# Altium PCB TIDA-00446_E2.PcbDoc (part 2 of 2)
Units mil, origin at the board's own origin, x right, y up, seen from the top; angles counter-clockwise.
Board outline 1780.03 x 5400.03 mil, 4 copper layers (Top Layer, GND, PWR, Bottom Layer), stack 79.834 mil thick; 192 components, 100 nets, 515 pads, 129 vias.
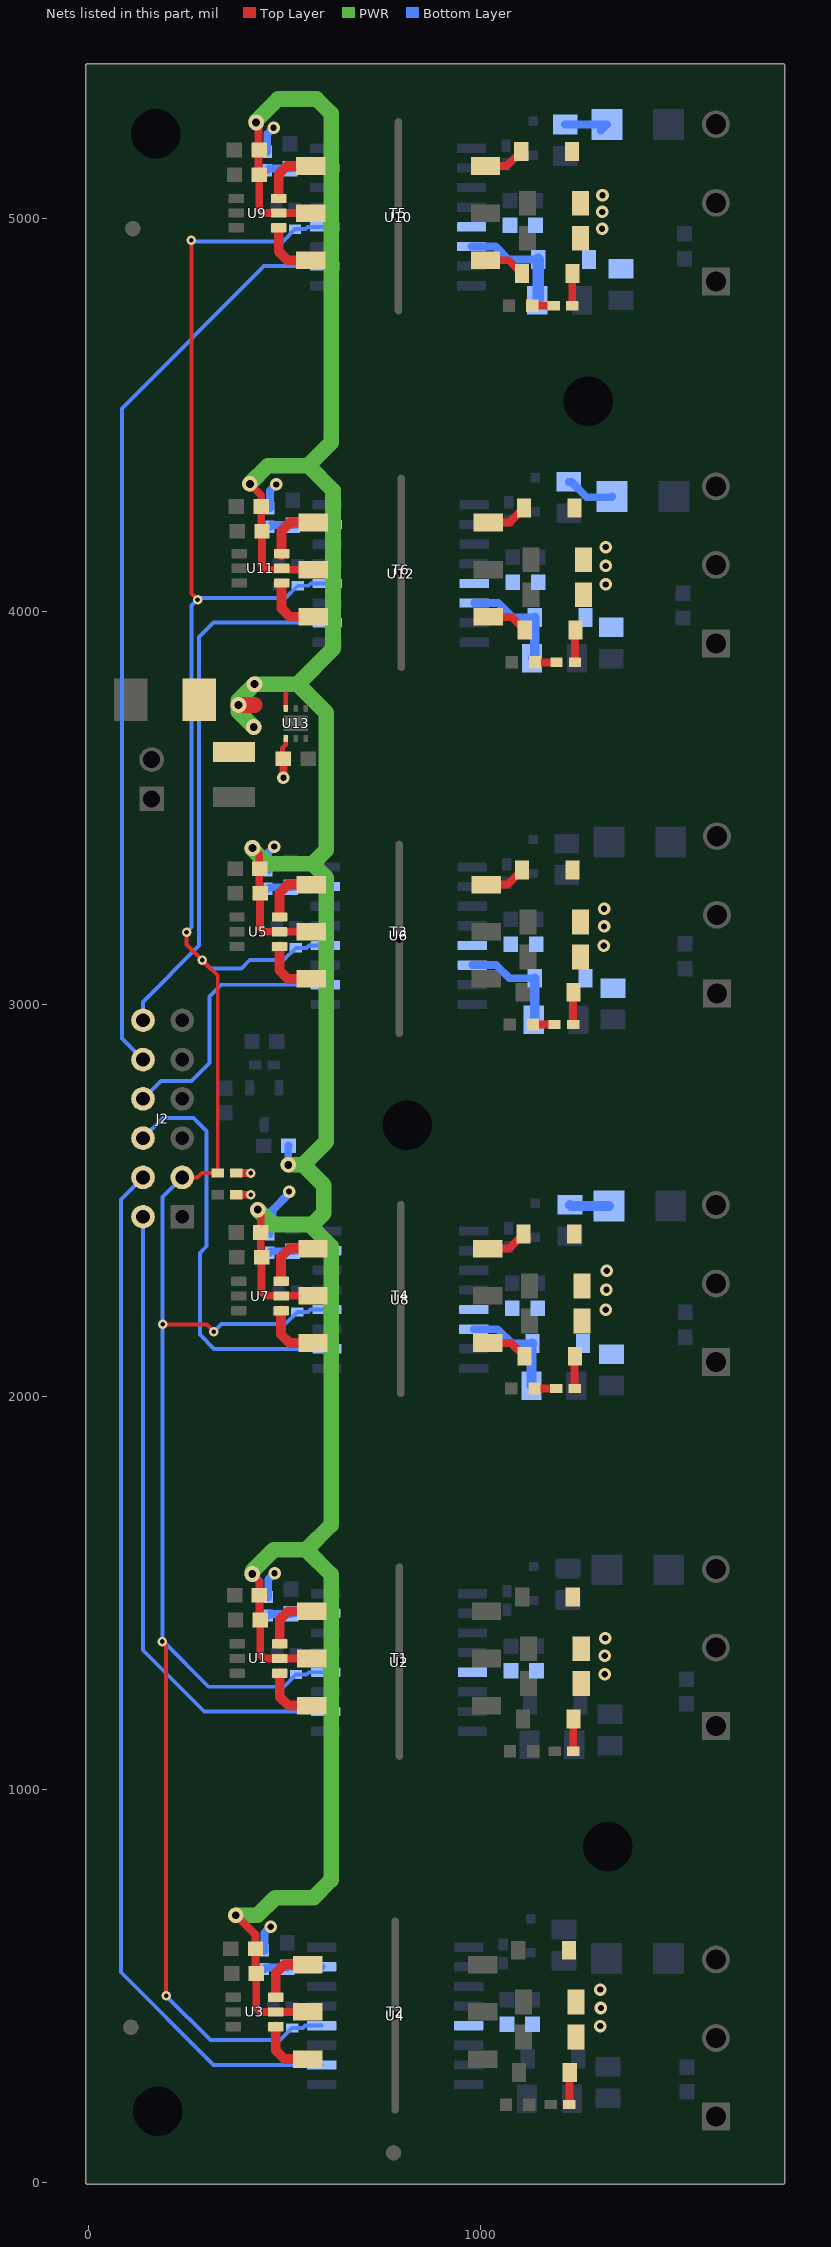
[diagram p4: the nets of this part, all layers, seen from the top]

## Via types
v1: diameter 32, hole 16, Top Layer to Bottom Layer, 85 vias
v2: diameter 24, hole 12, Top Layer to Bottom Layer, 30 vias
v3: diameter 40, hole 20, Top Layer to Bottom Layer, 12 vias
v4: diameter 19.68, hole 7.87, Top Layer to Bottom Layer, 2 vias

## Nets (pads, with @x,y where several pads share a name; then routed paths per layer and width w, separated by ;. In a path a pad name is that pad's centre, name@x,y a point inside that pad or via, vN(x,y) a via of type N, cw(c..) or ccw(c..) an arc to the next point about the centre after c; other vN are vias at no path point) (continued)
NetD17_2: D17.2 T3.6 | length 106.2
  Top Layer w20: T3.6@1014.13,3304.59 1068.1,3304.59 D17.2@1105.02,3341.51
NetD18_1: D18.1 R19.1 U6.6 | length 320.6
  Bottom Layer w20: 1019.06,3099.51 U6.6@978.5,3099.51 1039.49,3099.51 1073,3066 D18.1@1137.53,3066
  Bottom Layer w25: R19.1@1134.91,2960 1137.53,2962.62 D18.1@1137.53,3066
NetD18_2: D18.2 R20.1
NetD19_1: D19.1 R18.1 | length 54.9
  Top Layer w20: D19.1@1133.02,2948.51 R18.1@1187.87,2948.51
NetD21_2: D21.2 T4.4 | length 114.1
  Top Layer w20: T4.4@1018.13,2137.43 1077.1,2137.43 D21.2@1111.02,2103.51 ; D21.2@1108.52,2101.01 1110.02,2099.51 D21.2@1110.02,2094.51
NetD22_2: D22.2 R22.2 | length 100.5
  Bottom Layer w25: R22.2@1227,2489 1230,2486 D22.2@1326.26,2486
NetD23_2: D23.2 T4.6 | length 106.2
  Top Layer w20: T4.6@1018.13,2377.59 1072.1,2377.59 D23.2@1109.02,2414.51
NetD24_1: D24.1 R24.1 U8.6 | length 313.8
  Bottom Layer w20: 1023.06,2172.51 U8.6@982.5,2172.51 1043.49,2172.51 1080,2136 D24.1@1131.53,2136
  Bottom Layer w25: R24.1@1128.91,2028 1128.91,2133.38 D24.1@1131.53,2136
NetD24_2: D24.2 R25.1
NetD25_1: D25.1 R23.1 | length 54.9
  Top Layer w20: D25.1@1137.02,2021.51 R23.1@1191.87,2021.51
NetD27_2: D27.2 T5.4 | length 114.1
  Top Layer w20: T5.4@1012.13,4894.43 1071.1,4894.43 D27.2@1105.02,4860.51 ; D27.2@1102.52,4858.01 1104.02,4856.51 D27.2@1104.02,4851.51
NetD28_2: D28.2 R27.2 | length 128
  Bottom Layer w20: R27.2@1215,5240 D28.2@1321.13,5240 D28.2@1305.64,5224.51
NetD29_2: D29.2 T5.6 | length 106.2
  Top Layer w20: T5.6@1012.13,5134.59 1066.1,5134.59 D29.2@1103.02,5171.51
NetD30_1: D30.1 R29.1 U10.6 | length 288
  Bottom Layer w20: U10.6@976.5,4929.51 1037.49,4929.51 1071,4896 D30.1@1146.53,4896 ; R29.1@1143.91,4793 R29.1@1146.53,4795.62
  Bottom Layer w30: R29.1@1146.53,4795.62 D30.1@1146.53,4896
NetD30_2: D30.2 R30.1
NetD31_1: D31.1 R28.1 | length 54.9
  Top Layer w20: D31.1@1131.02,4778.51 R28.1@1185.87,4778.51
NetD33_2: D33.2 T6.4 | length 114.1
  Top Layer w20: T6.4@1019.13,3986.43 1078.1,3986.43 D33.2@1112.02,3952.51 ; D33.2@1109.52,3950.01 1111.02,3948.51 D33.2@1111.02,3943.51
NetD34_2: D34.2 R32.2 | length 127.5
  Bottom Layer w20: R32.2@1224,4330 1231,4330 1270,4291 1333.24,4291 D34.2@1334.75,4292.51
NetD35_2: D35.2 T6.6 | length 106.2
  Top Layer w20: T6.6@1019.13,4226.59 1073.1,4226.59 D35.2@1110.02,4263.51
NetD36_1: D36.1 R34.1 U12.6 | length 316.5
  Bottom Layer w20: 1024.06,4021.51 U12.6@983.5,4021.51 1044.49,4021.51 1081,3985 D36.1@1137.53,3985 ; R34.1@1130.91,3881 R34.1@1137.53,3887.62
  Bottom Layer w25: R34.1@1137.53,3887.62 D36.1@1137.53,3985
NetD36_2: D36.2 R35.1
NetD37_1: D37.1 R33.1 | length 54.9
  Top Layer w20: D37.1@1138.02,3870.51 R33.1@1192.87,3870.51
NetT1_1: T1.1 U1.3 | length 151.6
  Top Layer w25: U1.3@488.13,1371.4 488.13,1433.13 509.08,1454.08 T1.1@569.36,1454.08
NetT1_3: T1.3 U1.1 | length 151.1
  Top Layer w25: U1.1@488.13,1296.6 488.13,1235.87 510.08,1213.92 T1.3@569.36,1213.92
NetT2_1: T2.1 U3.3 | length 151.6
  Top Layer w25: U3.3@478.13,471.4 478.13,533.13 499.08,554.08 T2.1@559.36,554.08
NetT2_3: T2.3 U3.1 | length 151.1
  Top Layer w25: U3.1@478.13,396.6 478.13,335.87 500.08,313.92 T2.3@559.36,313.92
NetT3_1: T3.1 U5.3 | length 151.6
  Top Layer w25: U5.3@487.62,3221.91 487.62,3283.64 508.57,3304.59 T3.1@568.85,3304.59
NetT3_3: T3.3 U5.1 | length 151.1
  Top Layer w25: U5.1@487.62,3147.11 487.62,3086.38 509.57,3064.43 T3.3@568.85,3064.43
NetT4_1: T4.1 U7.3 | length 151.6
  Top Layer w25: U7.3@491.62,2294.91 491.62,2356.64 512.57,2377.59 T4.1@572.85,2377.59
NetT4_3: T4.3 U7.1 | length 151.1
  Top Layer w25: U7.1@491.62,2220.11 491.62,2159.38 513.57,2137.43 T4.3@572.85,2137.43
NetT5_1: T5.1 U9.3 | length 151.6
  Top Layer w25: U9.3@485.62,5051.91 485.62,5113.64 506.57,5134.59 T5.1@566.85,5134.59
NetT5_3: T5.3 U9.1 | length 151.1
  Top Layer w25: U9.1@485.62,4977.11 485.62,4916.38 507.57,4894.43 T5.3@566.85,4894.43
NetT6_1: T6.1 U11.3 | length 151.6
  Top Layer w25: U11.3@492.62,4143.91 492.62,4205.64 513.57,4226.59 T6.1@573.85,4226.59
NetT6_3: T6.3 U11.1 | length 151.1
  Top Layer w25: U11.1@492.62,4069.11 492.62,4008.38 514.57,3986.43 T6.3@573.85,3986.43
P3P3V: C20.1 R1.1 R6.1 R8.1 R16.2 R17.2 R21.1 R26.1 R31.1 U13.1 | length 643.9
  Top Layer w12: C20.1@497.5,3625 495,3627.5 495,3652.27 503.41,3660.68 U13.1@503.41,3676.61
  Top Layer w20: R17.2@377.62,2515 v2(414,2515) ; R16.2@377.62,2570 v2(414,2570) ; C20.1@497.5,3625 v1(497.5,3576.5) v1@499,3575
  Bottom Layer w20: R8.1@449,590.62 449,635 v1(465,651) ; R26.1@456.49,5171.13 456.49,5215.51 v1(472.49,5231.51) ; R6.1@458.49,3341.13 458.49,3385.51 v1(474.49,3401.51) ; R1.1@459,1490.62 459,1535 v1(475,1551) ; R21.1@462.49,2414.13 462.49,2453.75 470,2461.26 470,2476 512,2518 v1(512,2523) ; R31.1@463.49,4263.13 463.49,4307.51 v1(479.49,4323.51)
P3P3V_FLT_B_U: C11.1 R8.2 U4.15 | length 148.3
  Bottom Layer w20: R8.2@449,543.38 453.13,547.5 C11.1@507,547.5 508.5,549 U4.15@594.99,549
P3P3V_FLT_B_V: C34.1 R21.2 U8.15 | length 148.3
  Bottom Layer w20: R21.2@462.49,2366.89 466.62,2371.01 C34.1@520.49,2371.01 521.99,2372.51 U8.15@608.48,2372.51
P3P3V_FLT_B_W: C54.1 R31.2 U12.15 | length 148.3
  Bottom Layer w20: R31.2@463.49,4215.89 467.62,4220.01 C54.1@521.49,4220.01 522.99,4221.51 U12.15@609.48,4221.51
P3P3V_FLT_T_U: C2.1 R1.2 U2.15 | length 148.3
  Bottom Layer w20: R1.2@459,1443.38 463.13,1447.5 C2.1@517,1447.5 518.5,1449 U2.15@604.99,1449
P3P3V_FLT_T_V: C26.1 R6.2 U6.15 | length 148.3
  Bottom Layer w20: R6.2@458.49,3293.89 462.62,3298.01 C26.1@516.49,3298.01 517.99,3299.51 U6.15@604.48,3299.51
P3P3V_FLT_T_W: C46.1 R26.2 U10.15 | length 148.3
  Bottom Layer w20: R26.2@456.49,5123.89 460.62,5128.01 C46.1@514.49,5128.01 515.99,5129.51 U10.15@602.48,5129.51
P5V: C1.2 C5.2 C6.1 C10.2 C15.1 C19.1 C27.1 C33.2 C37.1 C43.2 C47.1 C53.2 C57.1 D13.1 R9.2 T1.2 T2.2 T3.2 T4.2 T5.2 T6.2 U1.2 U3.2 U5.2 U7.2 U9.2 U11.2 U13.6 | length 8504.4
  Top Layer w12: U13.6@503.41,3753.39 503.41,3789.41 504,3790
  Top Layer w20: v3(376,680) 377,680 426.5,630.5 C10.2@426.5,595 426.5,534 C15.1@428.5,532 428.5,444.5 439,434 U3.2@478.13,434 T2.2@559.36,434 ; v3(412,4325) 440.99,4296.01 C53.2@440.99,4267.51 440.99,4206.51 C57.1@442.99,4204.51 442.99,4117.01 453.49,4106.51 T6.2@573.85,4106.51 ; v3@425,3392 435.99,3381.01 435.99,3284.51 C27.1@437.99,3282.51 437.99,3195.01 448.49,3184.51 U5.2@487.62,3184.51 T3.2@568.85,3184.51 ; v3@425.51,1541.49 436.5,1530.5 C1.2@436.5,1495 436.5,1434 C6.1@438.5,1432 438.5,1344.5 449,1334 U1.2@488.13,1334 T1.2@569.36,1334 ; v3(428,5245) 433.99,5239.01 433.99,5114.51 C47.1@435.99,5112.51 435.99,5025.01 446.49,5014.51 U9.2@485.62,5014.51 T5.2@566.85,5014.51 ; v3@439.99,2481.01 C33.2@439.99,2418.51 439.99,2357.51 C37.1@441.99,2355.51 441.99,2268.01 452.49,2257.51 T4.2@572.85,2257.51
  Top Layer w40: v3(383,3762) 424,3762
  PWR w40: v3(376,680) 431.77,680 476.77,725 574,725 619,770 619,1548 556,1611 ; v3(412,4325) 458.51,4371.51 560.51,4371.51 ; v3(418,1549) 418,1556.23 472.77,1611 556,1611 ; v3(419,3398) 419,3394.77 456.26,3357.51 571.49,3357.51 ; v3(422,3706) 383,3745 v3(383,3762) 383,3774 v3(424,3815) 534,3815 ; v3(428,5245) 428,5249.25 483.75,5305 582,5305 619,5268 619,4430 560.51,4371.51 ; v3@432.28,2476.72 470,2439 564,2439 ; v3(510,2591) 548,2591 ; 534,3815 606.7,3742.3 606.7,3392.7 571.51,3357.51 ; 534,3815 624,3905 624,4308.02 560.51,4371.51 ; 548,2591 600.21,2538.79 600.21,2467.99 572.23,2440 563,2440 564,2439 ; 548,2591 606.7,2649.7 606.7,3322.3 571.49,3357.51 ; 556,1611 619,1674 619,2384 564,2439
  Bottom Layer w20: v3(510,2591) 510,2639.5 R9.2@510.5,2640
  other v3: 432,2477
P17V_BOT_U: C12.1 C13.1 C23.1 C65.1 D7.1 D9.1 R11.2 U4.5 | length 82.4
  Top Layer w20: R11.2@1225.62,198 1225.62,279.15 D7.1@1226.47,280
  other v1: 1304,398 1306,444 1304,491
P17V_BOT_V: C35.1 C36.1 C38.1 C67.1 D21.1 D23.1 R23.2 U8.5 | length 81.2
  Top Layer w20: R23.2@1239.11,2021.51 D21.1@1239.11,2102.66
  other v1: 1318,2222 1320,2273 1321,2321
P17V_BOT_W: C55.1 C56.1 C58.1 C69.1 D33.1 D35.1 R33.2 U12.5 | length 81.2
  Top Layer w20: R33.2@1240.11,3870.51 D33.1@1240.11,3951.66
  other v1: 1318,4069 1318,4116 1318,4164
P17V_TOP_U: C3.1 C4.1 C21.1 C64.1 D1.1 D3.1 R4.2 U2.5 | length 81.2
  Top Layer w20: R4.2@1235.62,1098 D1.1@1235.62,1179.15
  other v1: 1316,1294 1316,1341 1317,1386
P17V_TOP_V: C14.1 C25.1 C28.1 C66.1 D14.1 D17.1 R18.2 U6.5 | length 81.2
  Top Layer w20: R18.2@1235.11,2948.51 D14.1@1235.11,3029.66
  other v1: 1313,3149 1314,3198 1314,3243
P17V_TOP_W: C44.1 C45.1 C48.1 C68.1 D27.1 D29.1 R28.2 U10.5 | length 81.2
  Top Layer w20: R28.2@1233.11,4778.51 D27.1@1233.11,4859.66
  other v1: 1309,4975 1309.49,5017.51 1310,5060
PWM_BOT_U: J2.4 U4.10 | length 2655.9
  Bottom Layer w10: J2.4@140,2559 84,2503 84,535 320,299 U4.10@594.99,299
PWM_BOT_V: J2.6 U8.10 | length 1060.6
  Bottom Layer w10: J2.6@140,2659 191,2710 269,2710 302,2677 302,2383.64 285,2366.64 285,2322 285,2158.64 321.13,2122.51 U8.10@608.48,2122.51
PWM_BOT_W: J2.12 U12.10 | length 1376.8
  Bottom Layer w10: J2.12@140,2959 140,3006 283,3149 283,3935 319.51,3971.51 U12.10@609.48,3971.51
PWM_TOP_U: J2.2 U2.10 | length 1633.6
  Bottom Layer w10: J2.2@140,2459 140,1355 296,1199 U2.10@604.99,1199
PWM_TOP_V: J2.8 U6.10 | length 684.4
  Bottom Layer w10: J2.8@140,2759 186,2805 264,2805 309,2850 309,3020 338.51,3049.51 U6.10@604.48,3049.51
PWM_TOP_W: J2.10 U10.10 | length 2347
  Bottom Layer w10: J2.10@140,2859 86,2913 86,4517 448.51,4879.51 U10.10@602.48,4879.51
READY: C8.1 C17.1 C31.1 C41.1 C51.1 C61.1 J2.3 R16.1 U2.12 U4.12 U6.12 U8.12 U10.12 U12.12 | length 7078.2
  Top Layer w10: v2(189,1377) 199,1367 v2(199,475) ; v2(190,2185) 191,2184 302.51,2184 v2(320.25,2166.25) ; J2.3@240,2559 279,2559 290,2570 R16.1@330.38,2570 330.38,3072.64 v2(290.51,3112.51) 251,3152.02 v2(251,3183) ; v2(263,4945) 263,4046 v2(279,4030)
  Bottom Layer w10: v2(199,475) 312,362 488.62,362 C17.1@519.62,393 547,393 553,399 U4.12@594.99,399 ; J2.3@223,2559 J2.3@240,2559 190,2509 v2(190,2185) 190,1378 v2(189,1377) 192,1377 307,1262 498.62,1262 C8.1@529.62,1293 557,1293 563,1299 U2.12@604.99,1299 ; v2(251,3183) 264,3196 264,4015 v2(279,4030) ; v2(263,4945) 265.49,4942.51 496.11,4942.51 C51.1@527.11,4973.51 554.49,4973.51 560.49,4979.51 U10.12@602.48,4979.51 ; v2@283.51,4034.51 503.11,4034.51 C61.1@534.11,4065.51 561.49,4065.51 567.49,4071.51 U12.12@609.48,4071.51 ; v2(290.51,3112.51) 312.02,3091 390.36,3091 411.87,3112.51 498.11,3112.51 C31.1@529.11,3143.51 556.49,3143.51 562.49,3149.51 U6.12@604.48,3149.51 ; v2(320.25,2166.25) 339.51,2185.51 502.11,2185.51 C41.1@533.11,2216.51 560.49,2216.51 566.49,2222.51 U8.12@608.48,2222.51
pads on no net: FID1.1 FID2.1 FID3.1 FID4.1 FID5.1 FID6.1 H1.1 H2.1 H3.1 H4.1 H5.0 H6.0 H7.0 H8.0 H9.0 H10.1 LBL1.0 U2.4 U4.4 U6.4 U8.4 U10.4 U12.4 U13.2 U13.5

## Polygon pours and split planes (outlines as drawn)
NetD13_2 on Top Layer "Top Layer-No Net 1" (solid, pour order 75): 194,3620 194,3865 174,3885 69,3885 59,3875 59,3605 74,3590 184,3590 194,3600
P5V on Top Layer "GND" (solid, remove dead copper, pour order 96): 234,3860 234,3605 244,3595 424,3595 459,3630 459,3770 512.17,3770 518.43,3776.26 518.43,3845.57 494,3870 244,3870 234,3860
GND on Top Layer "Top Layer-No Net 2" (solid, remove dead copper, pour order 61): 499,3720 509,3730 614,3730 629,3715 629,3710 629,3700 629,3610 629,3585 629,3440 619,3430 474,3430 474,3500 474,3545 519,3545 539,3565 539,3645 549,3655 549,3690 544,3695 534,3695 504,3695 499,3700
GND on Top Layer "Top Layer-No Net 1" (solid, pour order 74): 482,3555 491,3546 491,3439 481,3429 129,3429 119,3439 119,3550 124,3555
ISO_GND_TOP_U on Top Layer "Top Layer-No Net" (solid, pour order 60): 1065,1362 975,1362 969,1356 969,1309 979,1299 1067,1299 1071,1295 1071,1245 1078,1238 1164,1238 1178,1252 1178,1429 1172,1435 1077,1435 1071,1429 1071,1364 1069,1362
ISO_GND_BOT_V on Top Layer "Top Layer-No Net" (solid, pour order 59): 1068.49,2285.51 978.49,2285.51 972.49,2279.51 972.49,2232.51 982.49,2222.51 1070.49,2222.51 1074.49,2218.51 1074.49,2173.51 1087,2161 1166.98,2161 1182,2176.02 1182,2354 1177.49,2358.51 1080.49,2358.51 1074.49,2352.51 1074.49,2287.51 1072.49,2285.51
ISO_GND_TOP_V on Top Layer "Top Layer-No Net" (solid, pour order 58): 1064.49,3212.51 974.49,3212.51 968.49,3206.51 968.49,3159.51 978.49,3149.51 1066.49,3149.51 1070.49,3145.51 1070.49,3103.51 1085,3089 1163.98,3089 1178,3103.02 1178,3280 1172.49,3285.51 1076.49,3285.51 1070.49,3279.51 1070.49,3214.51 1068.49,3212.51
ISO_GND_BOT_W on Top Layer "Top Layer-No Net" (solid, pour order 57): 1069.49,4134.51 979.49,4134.51 973.49,4128.51 973.49,4081.51 983.49,4071.51 1071.49,4071.51 1075.49,4067.51 1075.49,4024.51 1089,4011 1168.98,4011 1182.49,4024.51 1182.49,4194.51 1169.49,4207.51 1081.49,4207.51 1075.49,4201.51 1075.49,4136.51 1073.49,4134.51
ISO_GND_TOP_W on Top Layer "Top Layer-No Net" (solid, pour order 56): 1062.49,5042.51 972.49,5042.51 966.49,5036.51 966.49,4989.51 976.49,4979.51 1064.49,4979.51 1068.49,4975.51 1068.49,4931.51 1081,4919 1161.98,4919 1176,4933.02 1176,5110 1170.49,5115.51 1074.49,5115.51 1068.49,5109.51 1068.49,5044.51 1066.49,5042.51
ISO_GND_BOT_U on Top Layer "Top Layer-No Net" (solid, pour order 55): 1055,462 965,462 959,456 959,409 969,399 1057,399 1061,395 1061,347 1070,338 1154,338 1168,352 1168,522 1151,539 1071,539 1061,529 1061,464 1059,462
P17V_TOP_U on Top Layer "Top Layer-No Net" (solid, pour order 80): 1216,1157 1216,1524 1222,1530 1331,1530 1335,1526 1335,1154 1332,1151 1218,1151 1216,1153
P17V_BOT_U on Top Layer "Top Layer-No Net" (solid, pour order 81): 1218,320 1206,308 1206,250 1212,244 1320,244 1326,250 1326,615 1320.26,620.74 1207.74,620.74 1203,616 1203,528 1218,513
P17V_BOT_V on Top Layer "Top Layer-No Net" (solid, pour order 79): 1219.49,2080.51 1219.49,2447.51 1225.49,2453.51 1334.49,2453.51 1338.49,2449.51 1338.49,2077.51 1335.49,2074.51 1221.49,2074.51 1219.49,2076.51
P17V_TOP_V on Top Layer "Top Layer-No Net" (solid, pour order 78): 1215.49,3007.51 1215.49,3374.51 1221.49,3380.51 1330.49,3380.51 1334.49,3376.51 1334.49,3004.51 1331.49,3001.51 1217.49,3001.51 1215.49,3003.51
P17V_BOT_W on Top Layer "Top Layer-No Net" (solid, pour order 77): 1220.49,3929.51 1220.49,4296.51 1226.49,4302.51 1335.49,4302.51 1339.49,4298.51 1339.49,3926.51 1336.49,3923.51 1222.49,3923.51 1220.49,3925.51
P17V_TOP_W on Top Layer "Top Layer-No Net" (solid, pour order 76): 1213.49,4837.51 1213.49,5204.51 1219.49,5210.51 1328.49,5210.51 1332.49,5206.51 1332.49,4834.51 1329.49,4831.51 1215.49,4831.51 1213.49,4833.51
NetD10_2 on Bottom Layer "Top Layer-No Net" (solid, remove dead copper, pour order 49): 1218,343 1218,290 1222,286 1226,282 1264,282 1274,282 1281,275 1285,271 1292,264 1309,264 1356,264 1358,266 1362,270 1362,292 1362,342 1356,348 1241,348 1223,348 1219,344
NetD4_2 on Bottom Layer "Top Layer-No Net" (solid, remove dead copper, pour order 50): 1225,1237 1225,1184 1229,1180 1233,1176 1271,1176 1281,1176 1288,1169 1292,1165 1299,1158 1316,1158 1363,1158 1365,1160 1369,1164 1369,1186 1369,1236 1363,1242 1248,1242 1230,1242 1226,1238
NetD24_2 on Bottom Layer "Top Layer-No Net" (solid, remove dead copper, pour order 51): 1229,2159 1229,2106 1233,2102 1237,2098 1275,2098 1285,2098 1292,2091 1296,2087 1303,2080 1320,2080 1367,2080 1369,2082 1373,2086 1373,2108 1373,2158 1367,2164 1252,2164 1234,2164 1230,2160
NetD36_2 on Bottom Layer "Top Layer-No Net" (solid, remove dead copper, pour order 53): 1233,4004 1233,3951 1237,3947 1241,3943 1279,3943 1289,3943 1296,3936 1300,3932 1307,3925 1324,3925 1371,3925 1373,3927 1377,3931 1377,3953 1377,4003 1371,4009 1256,4009 1238,4009 1234,4005
NetD30_2 on Bottom Layer "Top Layer-No Net" (solid, remove dead copper, pour order 54): 1253,4924 1253,4871 1257,4867 1261,4863 1299,4863 1309,4863 1316,4856 1320,4852 1327,4845 1344,4845 1391,4845 1393,4847 1397,4851 1397,4873 1397,4923 1391,4929 1276,4929 1258,4929 1254,4925
ISO_GND_BOT_U on Bottom Layer "Top Layer-No Net" (solid, pour order 73): 1006,515 937,515 932,510 932,488 939,481 1008,481 1044,445 1161,445 1168,452 1168,520 1160,528 1032,528 1019,515
NetD18_2 on Bottom Layer "Top Layer-No Net" (solid, remove dead copper, pour order 52): 1231,3088 1231,3035 1235,3031 1239,3027 1277,3027 1287,3027 1294,3020 1298,3016 1305,3009 1322,3009 1369,3009 1371,3011 1375,3015 1375,3037 1375,3087 1369,3093 1254,3093 1236,3093 1232,3089
ISO_GND_TOP_W on Bottom Layer "Top Layer-No Net" (solid, pour order 72): 1013.49,5095.51 944.49,5095.51 939.49,5090.51 939.49,5068.51 946.49,5061.51 1015.49,5061.51 1051.49,5025.51 1168.49,5025.51 1175.49,5032.51 1175.49,5100.51 1167.49,5108.51 1039.49,5108.51 1026.49,5095.51
ISO_GND_BOT_W on Bottom Layer "Top Layer-No Net" (solid, pour order 71): 1020.49,4187.51 951.49,4187.51 946.49,4182.51 946.49,4160.51 953.49,4153.51 1022.49,4153.51 1058.49,4117.51 1175.49,4117.51 1182.49,4124.51 1182.49,4192.51 1174.49,4200.51 1046.49,4200.51 1033.49,4187.51
ISO_GND_TOP_V on Bottom Layer "Top Layer-No Net" (solid, pour order 70): 1015.49,3265.51 946.49,3265.51 941.49,3260.51 941.49,3238.51 948.49,3231.51 1017.49,3231.51 1053.49,3195.51 1170.49,3195.51 1177.49,3202.51 1177.49,3270.51 1169.49,3278.51 1041.49,3278.51 1028.49,3265.51
ISO_GND_BOT_V on Bottom Layer "Top Layer-No Net" (solid, pour order 63): 1019.49,2338.51 950.49,2338.51 945.49,2333.51 945.49,2311.51 952.49,2304.51 1021.49,2304.51 1057.49,2268.51 1174.49,2268.51 1181.49,2275.51 1181.49,2343.51 1173.49,2351.51 1045.49,2351.51 1032.49,2338.51
ISO_GND_TOP_U on Bottom Layer "Top Layer-No Net" (solid, pour order 62): 1016,1415 947,1415 942,1410 942,1388 949,1381 1018,1381 1054,1345 1171,1345 1178,1352 1178,1420 1170,1428 1042,1428 1029,1415
P17V_BOT_U on Bottom Layer "Top Layer-No Net" (solid, pour order 69): 1150,422 1043,422 1035,414 934,414 931,411 931,385 933,383 936,380 1159,380 1314,380 1320,386 1320,502 1314,508 1223,508 1218,503 1218,428 1212,422
P17V_TOP_U on Bottom Layer "Top Layer-No Net" (solid, pour order 68): 1160,1322 1053,1322 1045,1314 944,1314 941,1311 941,1285 943,1283 946,1280 1169,1280 1331,1280 1334,1283 1334,1398 1330,1402 1237,1402 1228,1393 1228,1328 1222,1322
P17V_BOT_V on Bottom Layer "Top Layer-No Net" (solid, pour order 67): 1163.49,2245.51 1056.49,2245.51 1048.49,2237.51 947.49,2237.51 944.49,2234.51 944.49,2208.51 946.49,2206.51 949.49,2203.51 1172.49,2203.51 1334.51,2203.51 1339,2208 1339,2335 1334.49,2339.51 1234.49,2339.51 1231.49,2336.51 1231.49,2251.51 1225.49,2245.51
P17V_TOP_V on Bottom Layer "Top Layer-No Net" (solid, pour order 66): 1159.48,3172.51 1052.48,3172.51 1044.48,3164.51 943.48,3164.51 940.48,3161.51 940.48,3135.51 942.48,3133.51 945.48,3130.51 1168.48,3130.51 1325.51,3130.51 1330,3135 1330,3257 1324,3263 1231,3263 1227.48,3259.48 1227.48,3178.51 1221.48,3172.51
P17V_BOT_W on Bottom Layer "Top Layer-No Net" (solid, pour order 65): 1164.49,4094.51 1057.49,4094.51 1049.49,4086.51 948.49,4086.51 945.49,4083.51 945.49,4057.51 947.49,4055.51 950.49,4052.51 1173.49,4052.51 1330.51,4052.51 1335,4057 1335,4180 1331,4184 1236,4184 1232.49,4180.49 1232.49,4100.51 1226.49,4094.51
P17V_TOP_W on Bottom Layer "Top Layer-No Net" (solid, pour order 64): 1157.49,5002.51 1050.49,5002.51 1042.49,4994.51 941.49,4994.51 938.49,4991.51 938.49,4965.51 940.49,4963.51 943.49,4960.51 1166.49,4960.51 1322.51,4960.51 1326,4964 1326,5089 1324,5091 1228,5091 1225.49,5088.49 1225.49,5008.51 1219.49,5002.51
ISO_GND_BOT_U on GND "Top Layer-No Net" (solid, remove dead copper, pour order 93): 932.5,665.5 932.5,123.5 959,97 1627.5,97 1666.5,136 1666.5,415 1652.5,429 1390,429 1370.5,448.5 1370.5,625 1309.5,686 953,686
ISO_GND_TOP_W on GND "Top Layer-No Net" (solid, remove dead copper, pour order 91): 939,5275 939,4718 957,4700 1642,4700 1665,4723 1665,5063 1651,5077 1379,5077 1369,5087 1369,5273 1352,5290 954,5290
ISO_GND_BOT_W on GND "Top Layer-No Net" (solid, remove dead copper, pour order 90): 946,4360 946,3825 971,3800 1644,3800 1665,3821 1665,4141 1651,4155 1384,4155 1369,4170 1369,4351 1352,4368 954,4368
ISO_GND_TOP_V on GND "Top Layer-No Net" (solid, remove dead copper, pour order 89): 940,3460 940,2914 974,2880 1639,2880 1668,2909 1668,3250 1654,3264 1387,3264 1372,3279 1372,3460 1355,3477 957,3477
ISO_GND_BOT_V on GND "Top Layer-No Net" (solid, remove dead copper, pour order 88): 945,2529 945,1983 981,1947 1630,1947 1665,1982 1665,2311 1651,2325 1390,2325 1369,2346 1369,2521 1352,2538 954,2538
ISO_GND_TOP_U on GND "Top Layer-No Net" (solid, remove dead copper, pour order 87): 942,1599 942,1052 960,1034 1665,1034 1665,1384 1651,1398 1392,1398 1369,1421 1369,1594 1352,1611 954,1611
GND on GND "GND" (solid, remove dead copper, pour order 95): 632,101 596,65 88,65 43,110 43,5228 100,5285 110,5295 620,5295 640,5275 640,4291 648,4283 648,3374 642,3368 642,2438 645,2435 646,2434 646,2421 646,713 630.84,697.84
P17V_BOT_W on PWR "Top Layer-No Net" (solid, remove dead copper, pour order 86): 946,4360 946,3825 971,3800 1643,3800 1665,3822 1665,4141 1651,4155 1384,4155 1369,4170 1369,4351 1352,4368 954,4368
P17V_TOP_W on PWR "Top Layer-No Net" (solid, remove dead copper, pour order 85): 939,5275 939,4719 958,4700 1644,4700 1665,4721 1665,5063 1651,5077 1379,5077 1369,5087 1369,5273 1352,5290 954,5290
P17V_TOP_V on PWR "Top Layer-No Net" (solid, remove dead copper, pour order 84): 940,3460 940,2914 974,2880 1639,2880 1668,2909 1668,3250 1654,3264 1387,3264 1372,3279 1372,3460 1355,3477 957,3477
P17V_BOT_V on PWR "Top Layer-No Net" (solid, remove dead copper, pour order 83): 946,2530 946,1982 981,1947 1630,1947 1665,1982 1665,2311 1651,2325 1390,2325 1369,2346 1369,2521 1352,2538 954,2538
P17V_TOP_U on PWR "Top Layer-No Net" (solid, remove dead copper, pour order 82): 942,1599 942,1052 960,1034 1658,1034 1665,1041 1665,1384 1651,1398 1392,1398 1369,1421 1369,1594 1352,1611 954,1611
P3P3V on PWR "GND" (solid, remove dead copper, pour order 94): 632,101 596,65 88,65 43,110 43,5228 100,5285 110,5295 620,5295 640,5275 640,4291 648,4283 648,3374 642,3368 642,2438 645,2435 646,2434 646,2421 646,1154 629.98,1137.98
P17V_BOT_U on PWR "Top Layer-No Net" (solid, remove dead copper, pour order 92): 932.5,665.5 932.5,123.5 959,97 1627.5,97 1666.5,136 1666.5,415 1652.5,429 1390,429 1370.5,448.5 1370.5,625 1309.5,686 953,686

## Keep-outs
Keep-Out Layer:
  circle w10: c178,181 r158.84
  circle w10: c173,5216 r158.84
  circle w10: c1274,4535 r158.84
  circle w10: c1324,855 r158.84
  circle w10: c813,2692 r158.84
  lines w10: 29,30 29,5360 1739,5360 1739,30 29,30
  text ".Layer_Name" at 532,-1562.49 h60
Multi-Layer:
  circle w6: c778,75 r49.2
  circle w6: c114,4975 r49.2
  circle w6: c109,395 r49.2

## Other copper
Top Layer:
  text ".layer_Name" at 547,-1552 h60
GND:
  text "GND" at 597,-1550 h60
PWR:
  text "PWR" at 582,-1549 h60
Bottom Layer:
  text ".Layer_Name" at 606,-1562 h60

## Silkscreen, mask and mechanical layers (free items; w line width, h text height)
Top Overlay:
  lines w6: 289,625 289,688 340.76,688 341.9,689.14 ; 290.31,507.05 290.31,295.69 344,242 ; 299,2166 299,2394 311,2406 ; 299,2173 299,2098 369,2028 442,1955 1383,1955 1383,2214 ; 300.26,5021.26 299,5020 299,4981 299,4870 461,4708 1386,4708 1386,4972 ; 306,1415 305,1414 305,1350 305,1189 473,1021 1391,1021 1391,1297 ; 310,4245 311,4246 311,4362 ; 311,4175 311,3983 409,3885 753,3885 ; 317,3262 317,3017 457,2877 1387,2877 1387,3146 ; 319,3355 319,3426 323,3430 1377,3430 1377,3421 ; 338,248 454,132 1388,132 1388,686 1387,687 1267,687 630,687 412,687 ; 338,1541 338,1593 350,1593 ; 343,5230 343,5271 1384,5271 1384,5254 ; 398,4359 399,4360 1385,4360 1385,4346 ; 415,1592 633,1592 1270,1592 1390,1592 ; 466,2471 499,2471 512,2484 ; 546,2507 558,2519 568,2519 1378,2519 1378,2493 ; 822,3884 907,3799 1386,3799 1386,4091 ; 1255,512 1255,519 1265,529 ; 1255,5093 1264,5093 1282,5111 ; 1261,1405 1261,1423 1266,1428 1275,1428 ; 1264,2334 1264,2341 1281,2358 ; 1266,3263 1266,3270 1277,3281 ; 1274,4176 1274,4181 1289,4196 ; 1389,1465 1389,1592
  text "C" at 1586,5350 h30
  text "E" at 1631,4656 h30
  text "C" at 1586,4432 h30
  text "LBL1" at 73,4182 h30
  text "E" at 1551,3731 h30
  text "5V" at 46,3707 h30 r90
  text "C" at 1589,3546 h30
  text "GND" at 45,3368 h30 r90
  text "12" at 115,3020 h30
  text "11" at 222,3019 h30
  text "E" at 1551,2841 h30
  text "C" at 1588,2600 h30
  text "1" at 236,2370 h30
  text "2" at 129,2369 h30
  text "E" at 1542,1896 h30
  text "REV : E2" at 185,1718 h40 r90
  text "TIDA-00446" at 120,1683 h40 r90
  text "C" at 1579,1677 h30
  text "E" at 1545,969 h30
  text "C" at 1586,682 h30
  text "E" at 1333,51 h30
  text ".layer_Name" at 573,-1550 h60
Bottom Overlay:
  circle w10: c979.9,647 r5.1
  circle w10: c983,1551 r4.12
  circle w10: c982,2473 r5.1
  circle w10: c979,3397 r3.16
  circle w10: c991,4317 r3.16
  circle w10: c971,5229 r6.71
  text ".Layer_Name" at 532,-1562.49 h60
Top Paste:
  text ".Layer_Name" at 520,-1565.49 h60
Bottom Paste:
  text ".Layer_Name" at 520,-1565.49 h60
Top Solder:
  text ".Layer_Name" at 548,-1573 h60
Bottom Solder:
  text ".Layer_Name" at 595,-1569 h60
M1 Board Outline:
  lines w10: -1,0 -1,5390 1769,5390 1769,0 0,0
M2 Board Dimensions:
  rectangle: -208.5,-924 -83.5,-799
  rectangle: -83.5,-1049 291.5,-924
  lines w7: -208.5,-924 791.5,-924 ; -83.5,-1049 -83.5,-799 ; 41.5,-1049 41.5,-799 ; 291.5,-1049 291.5,-799 ; 541.5,-1049 541.5,-799 ; -208.5,-1049 791.5,-1049 791.5,-799 -208.5,-799 -208.5,-1049
M3 3D STEP Top:
  text ".Layer_Name" at 532,-1562.49 h60
M4 3D STEP Bottom:
  text ".Layer_Name" at 532,-1562.49 h60
M5 Assembly Top:
  lines w6: 485,3557 485,3705 605,3705 605,3557 485,3557
  lines w10: -337,-1634.17 6263,-1634.17 ; -337,-1430.83 6265,-1430.83 ; -337,-1227.5 -337,-1837.5 3668,-1837.5 6265,-1837.5 6265,-1227.5 -336.5,-1227.5 -336.5,-1837.5 ; 2128,-1837.5 2128,-1227.5 ; 3395,-1430.83 3395,-1227.5 ; 4235,-1430.83 4235,-1227.5 ; 4857,-1844 4857,-1641.17
  text "COMPONENTS MARKED 'DNP' SHOULD NOT BE POPULATED." at 1108.5,-1022.5 h30
  text "ASSEMBLY VARIANT:" at 1108,-1138 h30
  text ".VariantName" at 2144,-1138 h30
  text "ALL ARTWORK VIEWED FROM TOP SIDE" at -273.5,-1359.67 h30
  text "BOARD #:" at 2203,-1359.67 h30
  text ".PRJ_Number" at 2748.5,-1359.67 h30
  text "REV:" at 3593,-1359.67 h30
  text ".PCB_Rev" at 3884.5,-1359.67 h30
  text "SVN REV:" at 4431,-1359.67 h30
  text ".VersionControl_RevNumber" at 4937,-1359.67 h30
  text ".layer_Name" at 490,-1542 h30
  text "LAYER NAME =" at -280,-1549 h30
  text ".plot_File_Name" at -282,-1738 h30
  text "GENERATED    :" at 2205,-1768.34 h30
  text ".Print_Date" at 3074.5,-1768.34 h30
  text ".Print_Time" at 3803.5,-1768.34 h30
  text "TEXAS INSTRUMENTS" at 5068,-1768.34 h30
M6 Assembly Bottom:
  circle w10: c411,2803 r7.62
  circle w10: c978,559 r6.08
  circle w10: c985,1516 r6.08
  circle w10: c987,2413 r6.08
  circle w10: c987,3305 r6.08
  circle w10: c989,4195 r6.08
  circle w10: c979,5137 r6.08
  lines w6: 562,182 1010,182 1010,592 564,592 562,590 562,182 ; 563,4760 563,5168 565,5170 1011,5170 1011,4760 563,4760 ; 569,1139 1017,1139 1017,1549 571,1549 569,1547 569,1139 ; 571,2036 1019,2036 1019,2446 573,2446 571,2444 571,2036 ; 571,2928 1019,2928 1019,3338 573,3338 571,3336 571,2928 ; 573,3818 1021,3818 1021,4228 575,4228 573,4226 573,3818
  lines w10: -337.5,-1431.33 6264.5,-1431.33 ; -335.5,-1634.67 6264.5,-1634.67 ; 1692.5,-1431.33 1692.5,-1228 ; 2532.5,-1431.33 2532.5,-1228 ; 3799.5,-1838 3799.5,-1228 ; 4688.5,-1838 6264,-1838 6264,-1228 -337.5,-1228 -337.5,-1838 2259.5,-1838 6264.5,-1838 6264.5,-1228
  text "COMPONENTS MARKED 'DNP' SHOULD NOT BE POPULATED." at 6057,-1022 h30
  text ".VariantName" at 5013,-1138 h30
  text "ASSEMBLY VARIANT:" at 6052,-1138 h30
  text "SVN REV:" at 1496.5,-1360.17 h30
  text ".PCB_Rev" at 2043,-1360.17 h30
  text "REV:" at 2334.5,-1360.17 h30
  text ".PRJ_Number" at 3179,-1360.17 h30
  text "BOARD #:" at 3724.5,-1360.17 h30
  text "PCB VIEWED FROM BOTTOM SIDE" at 6201,-1360.17 h30
  text "LAYER NAME =" at 6196,-1545 h30
  text ".Layer_Name" at 5423,-1552 h30
  text "IGNORE ->" at 2502.85,-1562.49 h30
  text ".Print_Time" at 2124,-1768.84 h30
  text ".Print_Date" at 2853,-1768.84 h30
  text "GENERATED    :" at 3722.5,-1768.84 h30
  text ".plot_File_Name" at 5395.5,-1768.84 h30
  text "PLOT NAME =" at 6201,-1768.84 h30
M9 Title Sheet:
  drawing of 57 lines, arcs and shapes, not listed
  text "1" at 694.84,7332.5 h70
  text "2" at 3190.5,7332.5 h70
  text "3" at 5679.84,7332.5 h70
  text "4" at 8186.51,7332.5 h70
  text "5" at 10685.5,7332.5 h70
  text "6" at 13190.5,7332.5 h70
  text "A" at -461.5,6189.5 h70
  text "A" at 14338.5,6189.5 h70
  text "B" at -461.5,3809.5 h70
  text "B" at 14338.5,3809.5 h70
  text "C" at -461.5,1434.5 h70
  text "C" at 14338.5,1434.5 h70
  text "PROJECT TITLE:" at 11298.5,-426.5 h45
  text ".PRJ_Title" at 11719,-563 h70
  text "DESIGNED FOR:" at 11298.5,-727.5 h45
  text ".PRJ_Customer" at 11348.5,-867.5 h70
  text "D" at -461.5,-935.5 h70
  text "D" at 14338.5,-935.5 h70
  text "FILE NAME:" at 11298.5,-1027.5 h45
  text ".PCB_File_Name_No_Path" at 11348.5,-1147.5 h70
  text "Texas Instruments (TI) and/or its licensors do not warrant the accuracy or completeness of this specification" at 6329,-1309.34 h45
  text "ENGINEER:" at 11298.5,-1317.5 h45
  text "LAYOUT BY:" at 12803.5,-1317.5 h45
  text "or any information contained therein. TI and/or its licensors do not warrant that this design will meet" at 6284.01,-1422 h45
  text ".PRJ_Engineer" at 11348.5,-1472.49 h70
  text ".PCB_Layout" at 12854,-1472.49 h70
  text "the specifications, will be suitable for your application or fit for any particular purpose, or will operate in" at 6284.01,-1534.67 h45
  text "ALTIUM DESIGNER VERSION:" at 12803.5,-1627.5 h45
  text "an implementation. TI and/or its licensors do not warrant that the design is production worthy. You should" at 6284.01,-1647.33 h45
  text "completely validate and test your design implementation to confirm the system functionality for your application." at 6329,-1760 h45
  text ".print_Scale" at 11348.5,-1760.83 h70
  text ".Application_BuildNumber" at 12854,-1760.83 h70
  text "2" at 3190.5,-1967.5 h70
  text "3" at 5679.84,-1967.5 h70
  text "4" at 8186.51,-1967.5 h70
  text "5" at 10685.5,-1967.5 h70
  text "6" at 13190.5,-1967.5 h70
M10 Fab Notes:
  drawing of 228 lines, arcs and shapes, not listed
  text "DESIGN INFORMATION" at 12336.02,6106 h60
  text "(REFER ALSO ARRAY/PANEL PROFILING INFORMATION)" at 11974.46,5944.29 h60
  text "BOARD SIZE" at 11288.46,5940 h60
  text "1769MIL" at 11750.78,5812.18 h60
  text "X" at 12256.46,5812.18 h60
  text "5390MIL" at 12487.78,5812.18 h60
  text "Number of Layers :" at 11691.46,5615 h60
  text "4" at 12786.27,5605 h60
  text "MIN. TRACK WIDTH:" at 11691.46,5476 h60
  text "10" at 12787.7,5476 h60
  text "MIL" at 12942.46,5476 h60
  text "MIN. CLEARANCE:" at 11691.46,5344 h60
  text "MIL" at 12942.46,5344 h60
  text "8" at 12780,5343 h60
  text "MIN. VIA DRILL SIZE:" at 11691.46,5212 h60
  text "MIL" at 12942.46,5212 h60
  text "7.874" at 12655,5206 h60
  text "5.90 MIL" at 12386.46,5070.29 h60
  text "MINIMUM ANNULAR RING" at 11362.23,5066 h60
  text "EXTERNAL" at 13094.46,5066 h60
  text "PER" at 11562.23,4948 h60
  text "IPC-D-275 CLASS 2 LEVEL C" at 11782.23,4948 h60
  text "MIL, HOLES" at 13270.46,4835.71 h60
  text "+/-" at 12878,4835 h60
  text "+/-" at 13732,4835 h60
  text "REGISTRATION TOLERANCES:" at 11362.23,4830 h60
  text "METAL" at 12562,4830 h60
  text "5" at 13138.2,4830 h60
  text "3" at 13971.2,4830 h60
  text "MIL" at 14087.46,4830 h60
  text "MATERIAL:" at 11287.46,4620.54 h60
  text "FR-4 High Tg" at 12273.9,4480.21 h60
  text "FR-408" at 11708.46,4471.64 h60
  text "OTHER" at 13196.46,4471.64 h60
  text "X" at 12113,4471 h60
  text "63 MIL (1.6mm) +/-10%" at 12028.56,4308.92 h60
  text "THICKNESS:" at 11362.23,4304.64 h60
  text "X" at 11900.4,4304.64 h60
  text "OTHER" at 13313.46,4304.64 h60
  text "TOLERANCE:" at 11362.23,4146.64 h60
  text "X" at 12201.53,4146.64 h60
  text "ANSI IPC-6012 TYPE 3 CLASS 2" at 12388.48,4146.64 h60
  text "OTHER +/-" at 12388.46,3990.64 h60
  text "BOW & TWIST:" at 11362.23,3833.64 h60
  text "X" at 12201.53,3833.64 h60
  text "ANSI IPC-6012 TYPE 3 CLASS 2" at 12388.48,3833.64 h60
  text "OTHER +/-" at 12388.46,3675.13 h60
  text "COPPER THICKNESS (FINISHED):" at 11287.46,3539.64 h60
  text "1.4MIL (1oz)" at 12167.46,3386.92 h60
  text "2MIL (1.4oz)" at 12934.46,3386.92 h60
  text "2.8MIL (2oz)" at 13661.46,3386.92 h60
  text "OUTER:" at 11644.46,3382.64 h60
  text "X" at 12039,3382 h60
  text "1.4MIL (1oz)" at 12167.46,3229.92 h60
  text "2.8MIL (2oz)" at 12934.46,3229.92 h60
  text "N/A" at 13661,3230.29 h60
  text "INNER SIGNAL:" at 11355.38,3225.64 h60
  text "X" at 12034,3223 h60
  text "DRILLING:" at 11287.46,3086.64 h60
  text "REFERENCE:" at 11362.23,2969.64 h60
  text "X" at 12010.46,2969.64 h60
  text "AS SHOWN" at 12197.46,2969.64 h60
  text "X" at 12911.46,2969.64 h60
  text "NC_DRILL FILES" at 13048.46,2969.64 h60
  text "PTH MIN COPPER THICKNESS:" at 11362.23,2811.64 h60
  text "X" at 12712.46,2811.64 h60
  text "1MIL" at 12849.46,2811.64 h60
  text "OTHER" at 13346.46,2811.64 h60
  text "BOARD FINISH:" at 11287.46,2652.64 h60
  text "SILKSCREEN:" at 11442.68,2534.64 h60
  text "X" at 12391.46,2534.64 h60
  text "TOP" at 12517.46,2534.64 h60
  text "X" at 12901.46,2534.64 h60
  text "BOTTOM" at 13028.46,2534.64 h60
  text "SILKSCREEN COLOR:" at 11442.68,2367.64 h60
  text "X" at 12390.42,2367.64 h60
  text "WHITE" at 12517.46,2367.64 h60
  text "OTHER" at 13028.46,2367.64 h60
  text "SOLDER RESIST COLOR:" at 11442.68,2197.64 h60
  text "X" at 12010.42,2038.44 h60
  text "GREEN" at 12137.46,2038.44 h60
  text "BLUE" at 12728.46,2038.44 h60
  text "OTHER" at 13266.46,2038.44 h60
  text "IMMERSION GOLD (ENIG)" at 12348.46,1849.92 h60
  text "ENEPIG" at 13686,1846.64 h60
  text "SURFACE FINISH:" at 11287.46,1845.64 h60
  text "X" at 12161.51,1845.64 h60
  text "IMM. TIN/SILVER OR EQUIV" at 11617,1688.64 h60
  text "OTHER" at 13048.46,1688.64 h60
  text "ARRAY/PANEL:" at 11287.46,1509.64 h60
  text "CUT AND TRIM PER MECH LAYER 1" at 12348.46,1505.35 h60
  text "N.C. ROUTE" at 12348.46,1353.64 h60
  text "X" at 13027.46,1353.64 h60
  text "V. SCORE" at 13214.46,1353.64 h60
  text "CERTIFICATION:" at 11287.46,1216.64 h60
  text "MATERIALS AND WORKMANSHIP FOR ALL PCBS" at 12012.46,1216.64 h60
  text "TO MEET OR EXCEED THE REQUIREMENTS OF:" at 12012.46,1118.64 h60
  text "X" at 11638.96,982.13 h60
  text "ANSI IPC-A-600F CLASS ->" at 11777.96,982.13 h60
  text "X" at 13417.02,982.13 h60
  text "2" at 13535.96,982.14 h60
  text "1" at 13220.96,980.64 h60
  text "3" at 13889.96,980.64 h60
  text "X" at 11641.02,822.64 h60
  text "UL 94V-0" at 11777.96,822.64 h60
  text "X" at 12453.02,822.64 h60
  text "RoHS" at 12589.96,822.64 h60
  text "OTHER" at 13234.36,822.64 h60
  text "PER ORDER" at 13631.42,822.64 h60
  text "VIA TENTING:" at 12505,689 h60
  text "X" at 13589,688 h60
  text "ADDITIONAL REQUIREMENTS:" at 11287.46,681.64 h60
  text "YES" at 13054.67,679.92 h60
  text "NO" at 13419.47,674.69 h60
  text "MICROSECTION:" at 11362.23,566.64 h60
  text "YES" at 12267.96,566.64 h60
  text "IMPEDANCE CONTROL:" at 12527,560 h60
  text "YES" at 13511,559 h60
  text "X" at 14053,552 h60
  text "NO" at 13886.47,541.69 h60
  text "REQUIRED" at 13129.46,410.49 h60
  text "BARE BOARD ELEC. TEST:" at 11362.23,407.64 h60
  text "NONE" at 12667.96,407.64 h60
  text "X" at 13002.46,407.64 h60
  text "PER ORDER" at 13721.46,407.64 h60
  text "MANUFACTURER'S UL:" at 11362.23,250.64 h60
  text "RAIL" at 12527.96,246.35 h60
  text "METAL" at 13019.77,246.35 h60
  text "X" at 13395,246 h60
  text "SILK" at 13531.46,246.35 h60
M11 Gerber Information:
  lines w10: -337,-1634.17 6263,-1634.17 ; -337,-1430.83 6265,-1430.83 ; -337,-1227.5 -337,-1837.5 3668,-1837.5 6265,-1837.5 6265,-1227.5 -336.5,-1227.5 -336.5,-1837.5 ; 2128,-1837.5 2128,-1227.5 ; 3395,-1430.83 3395,-1227.5 ; 4235,-1430.83 4235,-1227.5 ; 4857,-1844 4857,-1641.17
  text "BOARD #:" at 2203,-1359.67 h60
  text ".PRJ_Number" at 2748.5,-1359.67 h60
  text "REV:" at 3593,-1359.67 h60
  text ".PCB_Rev" at 3884.5,-1359.67 h60
  text "SVN REV:" at 4431,-1359.67 h60
  text ".VersionControl_RevNumber" at 4937,-1359.67 h60
  text "ALL ARTWORK VIEWED FROM TOP SIDE" at -274.5,-1365.67 h60
  text "LAYER NAME =" at -276,-1549 h60
  text ".plot_File_Name" at -284,-1748 h60
  text "GENERATED    :" at 2205,-1768.34 h60
  text ".Print_Date" at 3074.5,-1768.34 h60
  text ".Print_Time" at 3803.5,-1768.34 h60
  text "TEXAS INSTRUMENTS" at 5068,-1768.34 h60
M12 Stackup:
  lines w6: 11315,6756 13865,6756 ; 11315,6860.4 13865,6860.4 ; 11255,6271 ccw(c11289,6271) 11289,6237 13891,6237 ccw(c13891,6271) 13925,6271 13925,6977 ccw(c13891,6977) 13891,7011 11289,7011 ccw(c11289,6977) 11255,6977 11255,6271
  text "Layer Stack Up Detail for: TIDA-00446-E2" at 11315,6893.1 h57
  text "Layer" at 11315,6821.4 h24
  text "Gerber" at 12210.81,6821.4 h24
  text "Copper" at 12774.33,6821.4 h24
  text "Dielectric" at 13377.04,6821.4 h24
  text "Name" at 11315,6773.4 h24
  text "Document" at 12210.81,6773.4 h24
  text "Thickness" at 12774.33,6773.4 h24
  text "Material" at 13377.04,6773.4 h24
  text "Top Solder Mask" at 11315,6680.44 h34
  text "(.GTS)" at 12210.81,6680.44 h34
  text "Solder Resist" at 13377.04,6680.44 h34
  text "Top Layer" at 11315,6583.69 h34
  text "(.GTL)" at 12210.81,6583.69 h34
  text "1.4mil" at 12774.33,6583.69 h34
  text "FR-4 Hg Tg" at 13406,6583 h34
  text "FR-4 Hg Tg" at 13405,6518 h34
  text "(.G1)" at 12214.81,6516.69 h34
  text "1.4mil" at 12775.33,6512.69 h34
  text "GND" at 11319,6510 h34
  text "FR-4 Hg Tg" at 13406,6453 h34
  text "1.4mil" at 12778.33,6446.69 h34
  text "(.G2)" at 12214.81,6443.69 h34
  text "PWR" at 11320,6434 h34
  text "FR-4 Hg Tg" at 13408,6364 h34
  text "Bottom Layer" at 11321,6354 h34
  text "(.GBL)" at 12219,6353 h34
  text "1.4mil" at 12779,6347 h34
  text "Solder Resist" at 13371,6280 h34
  text "(.GBS)" at 12216,6273 h34
  text "Bottom Solder Mask" at 11318,6268 h34
M13 Component Bodies Top:
  text ".Layer_Name" at 532,-1562.49 h60
M14 Component Bodies Bottom:
  text ".Layer_Name" at 532,-1562.49 h60
M15 Courtyards Top:
  text ".Layer_Name" at 532,-1562.49 h60
M16 Courtyards Bottom:
  text ".Layer_Name" at 532,-1562.49 h60
Drill Drawing:
  text ".legend" at 2235,2982 h60
  text "Drill Table" at 2232,2811 h60
  text "FOR 7.874MIL DRILL +0/-7.874MIL" at 2261,2604 h60
  text "FOR 12MIL DRILL +0/-12MIL" at 2258,2501 h60
  text "FOR 16MIL DRILL +0/-16MIL" at 2259,2397 h60
  text "FOR PTH DRILL +/-3MIL" at 2259,2279 h60
  text "FOR NPTH DRILL +/-2MIL" at 2265,2173 h60
  text ".layer_Name" at 637,-1546 h60

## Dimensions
0,0 to -1,5390 on M2 Board Dimensions
0,0 to 1769,0 on M2 Board Dimensions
